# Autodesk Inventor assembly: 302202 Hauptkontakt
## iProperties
Created: 2006-07
Part Number: 302202 Hauptkontakt
Document SubType Name: Assembly
Designer: I.Baliuc
Manufacturer: Standard
Standards Organization: Custom
Description: Hauptkontakt HSLT 18KA
Cost Center: 111,819 kg
Authority: 15486753 mm^3
Mass: 110237 g
Surface Area: 29604.2 cm^2
Volume: 15128.6 cm^3
Density: 7.28664 g/cm^3
Title: Hauptkontakt
Company: Mayer & Müller AG Schaltgeräte
Zweck: Motorantrieb
SaveDate: 2006-11-03
SaveTime: 00:22
TotalMass: 111,819 kg
TotalVolume: 15486753 mm^3
Author: T.Messerschmitt
Revision Number: 302202
